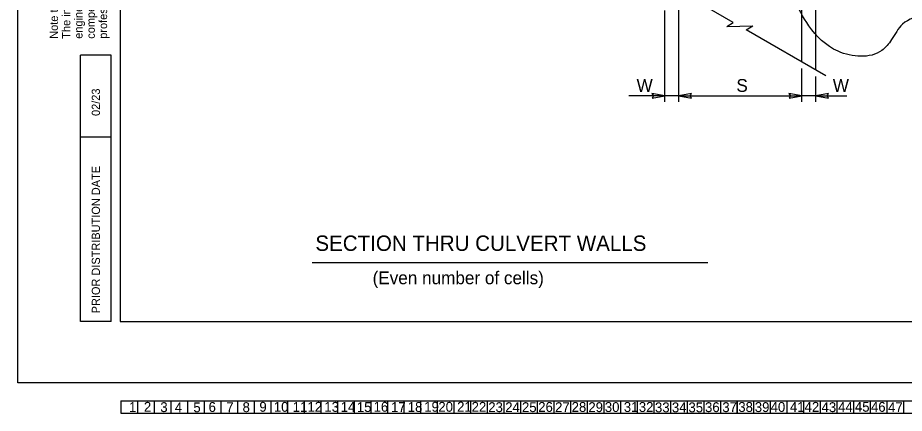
# Model space of a CAD drawing. Extents: x 0 to 2.83, y -0.03 to 1.83.
# Drawn here: x 0 to 0.902, y -0.031 to 0.371 of the extents above; entities that cross this region are included whole.
import ezdxf

# ---------------------------------------------------------------- set-up
doc = ezdxf.new("R2010")
doc.units = 0
for name, color, linetype in [('1', 7, 'Continuous'), ('10', 7, 'Continuous'), ('11', 7, 'Continuous'), ('12', 7, 'Continuous'), ('13', 7, 'Continuous'), ('14', 7, 'Continuous'), ('15', 7, 'Continuous'), ('16', 7, 'Continuous'), ('17', 7, 'Continuous'), ('18', 7, 'Continuous'), ('19', 7, 'Continuous'), ('2', 7, 'Continuous'), ('20', 7, 'Continuous'), ('21', 7, 'Continuous'), ('22', 7, 'Continuous'), ('23', 7, 'Continuous'), ('24', 7, 'Continuous'), ('25', 7, 'Continuous'), ('26', 7, 'Continuous'), ('27', 7, 'Continuous'), ('28', 7, 'Continuous'), ('29', 7, 'Continuous'), ('3', 7, 'Continuous'), ('30', 7, 'Continuous'), ('31', 7, 'Continuous'), ('32', 7, 'Continuous'), ('33', 7, 'Continuous'), ('34', 7, 'Continuous'), ('35', 7, 'Continuous'), ('36', 7, 'Continuous'), ('37', 7, 'Continuous'), ('38', 7, 'Continuous'), ('39', 7, 'Continuous'), ('4', 7, 'Continuous'), ('40', 7, 'Continuous'), ('41', 7, 'Continuous'), ('42', 7, 'Continuous'), ('43', 7, 'Continuous'), ('44', 7, 'Continuous'), ('45', 7, 'Continuous'), ('46', 7, 'Continuous'), ('47', 7, 'Continuous'), ('5', 7, 'Continuous'), ('54', 7, 'Continuous'), ('55', 7, 'Continuous'), ('6', 7, 'Continuous'), ('62', 7, 'Continuous'), ('63', 7, 'Continuous'), ('7', 7, 'Continuous'), ('8', 7, 'Continuous'), ('9', 7, 'Continuous'), ('Default', 7, 'Continuous')]:
    doc.layers.add(name, color=color, linetype=linetype)

msp = doc.modelspace()

# ---------------------------------------------------------------- linework, layer by layer
at = {"layer": '54'}
for points in [[(0.65794, 0.29184), (0.64495, 0.29422), (0.64646, 0.29184), (0.6451, 0.28944)], [(0.67226, 0.29184), (0.68525, 0.28947), (0.68375, 0.29184), (0.6851, 0.29424)], [(0.79726, 0.29184), (0.78427, 0.29422), (0.78578, 0.29184), (0.78442, 0.28944)], [(0.81159, 0.29184), (0.82458, 0.28947), (0.82307, 0.29184), (0.82443, 0.29424)]]:
    msp.add_lwpolyline(points, close=True, dxfattribs=at)
at = {"layer": '55'}
for p, q in [((0.7276, 0.36663), (0.58472, 0.44912)), ((0.65794, 0.28577), (0.65794, 0.37876)), ((0.67226, 0.28577), (0.67226, 0.37951)), ((0.72113, 0.36236), (0.7276, 0.36663)), ((0.72113, 0.36236), (0.74745, 0.36319)), ((0.74097, 0.35891), (0.74745, 0.36319)), ((0.82174, 0.31229), (0.74097, 0.35891)), ((0.79726, 0.28577), (0.79726, 0.31975)), ((0.81159, 0.28577), (0.81159, 0.31148)), ((0.65794, 0.29184), (0.62161, 0.29184)), ((0.67226, 0.29184), (0.65794, 0.29184)), ((0.67226, 0.29184), (0.79726, 0.29184)), ((0.81159, 0.29184), (0.79726, 0.29184)), ((0.81159, 0.29184), (0.84317, 0.29184))]:
    msp.add_line(p, q, dxfattribs=at)
msp.add_spline([(0.95184, 0.37351), (0.94161, 0.37351), (0.92297, 0.37345), (0.89978, 0.36478), (0.88869, 0.34904), (0.87866, 0.33797), (0.83439, 0.3372), (0.80458, 0.36301), (0.77828, 0.42143), (0.75487, 0.48444)], degree=3, dxfattribs=at)
at = {"layer": '62'}
for p, q in [((0.10494, -0.01804), (1.17174, -0.01804)), ((0.10494, -0.01804), (0.10494, -0.03074)), ((0.10496, -0.0181), (1.17175, -0.0181)), ((0.10496, -0.0181), (0.10496, -0.0308)), ((0.12188, -0.01804), (0.12188, -0.03074)), ((0.12189, -0.0181), (0.12189, -0.0308)), ((0.13881, -0.01804), (0.13881, -0.03074)), ((0.13882, -0.0181), (0.13882, -0.0308)), ((0.15574, -0.01804), (0.15574, -0.03074)), ((0.15576, -0.0181), (0.15576, -0.0308)), ((0.17267, -0.01804), (0.17267, -0.03074)), ((0.17269, -0.0181), (0.17269, -0.0308)), ((0.18961, -0.01804), (0.18961, -0.03074)), ((0.18962, -0.0181), (0.18962, -0.0308)), ((0.20654, -0.01804), (0.20654, -0.03074)), ((0.20656, -0.0181), (0.20656, -0.0308)), ((0.22348, -0.01804), (0.22348, -0.03074)), ((0.22349, -0.0181), (0.22349, -0.0308)), ((0.24041, -0.01804), (0.24041, -0.03074)), ((0.24042, -0.0181), (0.24042, -0.0308)), ((0.25734, -0.01804), (0.25734, -0.03074)), ((0.25736, -0.0181), (0.25736, -0.0308)), ((0.27427, -0.01804), (0.27427, -0.03074)), ((0.27429, -0.0181), (0.27429, -0.0308)), ((0.29121, -0.01804), (0.29121, -0.03074)), ((0.29122, -0.0181), (0.29122, -0.0308)), ((0.30814, -0.01804), (0.30814, -0.03074)), ((0.30816, -0.0181), (0.30816, -0.0308)), ((0.32508, -0.01804), (0.32508, -0.03074)), ((0.32509, -0.0181), (0.32509, -0.0308)), ((0.34201, -0.01804), (0.34201, -0.03074)), ((0.34202, -0.0181), (0.34202, -0.0308)), ((0.35894, -0.01804), (0.35894, -0.03074)), ((0.35896, -0.0181), (0.35896, -0.0308)), ((0.37588, -0.01804), (0.37588, -0.03074)), ((0.37589, -0.0181), (0.37589, -0.0308)), ((0.39281, -0.01804), (0.39281, -0.03074)), ((0.39282, -0.0181), (0.39282, -0.0308)), ((0.40974, -0.01804), (0.40974, -0.03074)), ((0.40976, -0.0181), (0.40976, -0.0308)), ((0.42668, -0.01804), (0.42668, -0.03074)), ((0.42669, -0.0181), (0.42669, -0.0308)), ((0.44361, -0.01804), (0.44361, -0.03074)), ((0.44362, -0.0181), (0.44362, -0.0308)), ((0.46054, -0.01804), (0.46054, -0.03074)), ((0.46056, -0.0181), (0.46056, -0.0308)), ((0.47748, -0.01804), (0.47748, -0.03074)), ((0.47749, -0.0181), (0.47749, -0.0308)), ((0.49441, -0.01804), (0.49441, -0.03074)), ((0.49442, -0.0181), (0.49442, -0.0308)), ((0.51134, -0.01804), (0.51134, -0.03074)), ((0.51136, -0.0181), (0.51136, -0.0308)), ((0.52828, -0.01804), (0.52828, -0.03074)), ((0.52829, -0.0181), (0.52829, -0.0308)), ((0.54521, -0.01804), (0.54521, -0.03074)), ((0.54522, -0.0181), (0.54522, -0.0308)), ((0.56214, -0.01804), (0.56214, -0.03074)), ((0.56216, -0.0181), (0.56216, -0.0308)), ((0.57908, -0.01804), (0.57908, -0.03074)), ((0.57909, -0.0181), (0.57909, -0.0308)), ((0.59601, -0.01804), (0.59601, -0.03074)), ((0.59602, -0.0181), (0.59602, -0.0308)), ((0.61294, -0.01804), (0.61294, -0.03074)), ((0.61296, -0.0181), (0.61296, -0.0308)), ((0.62988, -0.01804), (0.62988, -0.03074)), ((0.62989, -0.0181), (0.62989, -0.0308)), ((0.64681, -0.01804), (0.64681, -0.03074)), ((0.64682, -0.0181), (0.64682, -0.0308)), ((0.66374, -0.01804), (0.66374, -0.03074)), ((0.66376, -0.0181), (0.66376, -0.0308)), ((0.68068, -0.01804), (0.68068, -0.03074)), ((0.68069, -0.0181), (0.68069, -0.0308)), ((0.69761, -0.01804), (0.69761, -0.03074)), ((0.69762, -0.0181), (0.69762, -0.0308)), ((0.71454, -0.01804), (0.71454, -0.03074)), ((0.71456, -0.0181), (0.71456, -0.0308)), ((0.73147, -0.01804), (0.73147, -0.03074)), ((0.73149, -0.0181), (0.73149, -0.0308)), ((0.74841, -0.01804), (0.74841, -0.03074)), ((0.74842, -0.0181), (0.74842, -0.0308)), ((0.76534, -0.01804), (0.76534, -0.03074)), ((0.76536, -0.0181), (0.76536, -0.0308)), ((0.78228, -0.01804), (0.78228, -0.03074)), ((0.78229, -0.0181), (0.78229, -0.0308)), ((0.79921, -0.01804), (0.79921, -0.03074)), ((0.79922, -0.0181), (0.79922, -0.0308)), ((0.81614, -0.01804), (0.81614, -0.03074)), ((0.81616, -0.0181), (0.81616, -0.0308)), ((0.83308, -0.01804), (0.83308, -0.03074)), ((0.83309, -0.0181), (0.83309, -0.0308)), ((0.85001, -0.01804), (0.85001, -0.03074)), ((0.85002, -0.0181), (0.85002, -0.0308)), ((0.86694, -0.01804), (0.86694, -0.03074)), ((0.86695, -0.0181), (0.86695, -0.0308)), ((0.88388, -0.01804), (0.88388, -0.03074)), ((0.88389, -0.0181), (0.88389, -0.0308)), ((0.90081, -0.01804), (0.90081, -0.03074)), ((0.90082, -0.0181), (0.90082, -0.0308)), ((0.10494, -0.03074), (1.17174, -0.03074)), ((0.10496, -0.0308), (1.17175, -0.0308))]:
    msp.add_line(p, q, dxfattribs=at)
at = {"layer": '63'}
for p, q in [((0, 0), (0, 1.83333)), ((2.83333, 0), (0, 0))]:
    msp.add_line(p, q, dxfattribs=at)
at = {"layer": 'Default'}
for p, q in [((0.79726, 0.32642), (0.79726, 0.41983)), ((0.81159, 0.31815), (0.81159, 0.41202)), ((0.06381, 0.06244), (0.06381, 0.33328)), ((0.09506, 0.33328), (0.06381, 0.33328)), ((0.09506, 0.06244), (0.09506, 0.33328)), ((0.09506, 0.24994), (0.06381, 0.24994)), ((0.29945, 0.12254), (0.70177, 0.12254)), ((0.09506, 0.06244), (0.06381, 0.06244))]:
    msp.add_line(p, q, dxfattribs=at)
msp.add_lwpolyline([(2.72918, 1.77077), (0.10418, 1.77077), (0.10418, 0.06244), (2.72918, 0.06244)], close=True, dxfattribs=at)

# ---------------------------------------------------------------- texts
at = {"layer": '1'}
for p in [(0.11316, -0.02944), (0.11317, -0.02949)]:
    msp.add_text('1', height=0.01, dxfattribs=at).set_placement(p)
at = {"layer": '10'}
for p in [(0.26046, -0.02928), (0.26047, -0.02934)]:
    msp.add_text('10', height=0.01, dxfattribs=at).set_placement(p)
at = {"layer": '11'}
for p in [(0.2796, -0.02937), (0.27961, -0.02942)]:
    msp.add_text('11', height=0.01, dxfattribs=at).set_placement(p)
at = {"layer": '12'}
for p in [(0.29469, -0.02925), (0.29471, -0.0293)]:
    msp.add_text('12', height=0.01, dxfattribs=at).set_placement(p)
at = {"layer": '13'}
for p in [(0.31181, -0.02928), (0.31182, -0.02933)]:
    msp.add_text('13', height=0.01, dxfattribs=at).set_placement(p)
at = {"layer": '14'}
for p in [(0.32844, -0.02939), (0.32846, -0.02944)]:
    msp.add_text('14', height=0.01, dxfattribs=at).set_placement(p)
at = {"layer": '15'}
for p in [(0.34488, -0.02946), (0.34489, -0.02951)]:
    msp.add_text('15', height=0.01, dxfattribs=at).set_placement(p)
at = {"layer": '16'}
for p in [(0.3619, -0.02918), (0.36191, -0.02923)]:
    msp.add_text('16', height=0.01, dxfattribs=at).set_placement(p)
at = {"layer": '17'}
for p in [(0.3797, -0.02946), (0.37971, -0.02951)]:
    msp.add_text('17', height=0.01, dxfattribs=at).set_placement(p)
at = {"layer": '18'}
for p in [(0.39663, -0.02938), (0.39664, -0.02943)]:
    msp.add_text('18', height=0.01, dxfattribs=at).set_placement(p)
at = {"layer": '19'}
for p in [(0.4134, -0.02918), (0.41342, -0.02923)]:
    msp.add_text('19', height=0.01, dxfattribs=at).set_placement(p)
at = {"layer": '2'}
for p in [(0.12828, -0.02928), (0.12829, -0.02934)]:
    msp.add_text('2', height=0.01, dxfattribs=at).set_placement(p)
at = {"layer": '20'}
for p in [(0.42774, -0.02926), (0.42776, -0.02931)]:
    msp.add_text('20', height=0.01, dxfattribs=at).set_placement(p)
at = {"layer": '21'}
for p in [(0.44688, -0.02909), (0.44689, -0.02914)]:
    msp.add_text('21', height=0.01, dxfattribs=at).set_placement(p)
at = {"layer": '22'}
for p in [(0.46158, -0.02929), (0.46159, -0.02934)]:
    msp.add_text('22', height=0.01, dxfattribs=at).set_placement(p)
at = {"layer": '23'}
for p in [(0.47852, -0.02958), (0.47853, -0.02963)]:
    msp.add_text('23', height=0.01, dxfattribs=at).set_placement(p)
at = {"layer": '24'}
for p in [(0.49576, -0.02958), (0.49577, -0.02963)]:
    msp.add_text('24', height=0.01, dxfattribs=at).set_placement(p)
at = {"layer": '25'}
for p in [(0.51281, -0.02958), (0.51282, -0.02963)]:
    msp.add_text('25', height=0.01, dxfattribs=at).set_placement(p)
at = {"layer": '26'}
for p in [(0.52931, -0.02936), (0.52932, -0.02941)]:
    msp.add_text('26', height=0.01, dxfattribs=at).set_placement(p)
at = {"layer": '27'}
for p in [(0.54648, -0.02958), (0.54649, -0.02963)]:
    msp.add_text('27', height=0.01, dxfattribs=at).set_placement(p)
at = {"layer": '28'}
for p in [(0.56333, -0.02938), (0.56334, -0.02943)]:
    msp.add_text('28', height=0.01, dxfattribs=at).set_placement(p)
at = {"layer": '29'}
for p in [(0.58032, -0.02956), (0.58034, -0.02961)]:
    msp.add_text('29', height=0.01, dxfattribs=at).set_placement(p)
at = {"layer": '3'}
for p in [(0.145, -0.02955), (0.14501, -0.02961)]:
    msp.add_text('3', height=0.01, dxfattribs=at).set_placement(p)
at = {"layer": '30'}
for p in [(0.59706, -0.02946), (0.59707, -0.02951)]:
    msp.add_text('30', height=0.01, dxfattribs=at).set_placement(p)
at = {"layer": '31'}
for p in [(0.61636, -0.02938), (0.61637, -0.02943)]:
    msp.add_text('31', height=0.01, dxfattribs=at).set_placement(p)
at = {"layer": '32'}
for p in [(0.63163, -0.02938), (0.63165, -0.02943)]:
    msp.add_text('32', height=0.01, dxfattribs=at).set_placement(p)
at = {"layer": '33'}
for p in [(0.64808, -0.02978), (0.64809, -0.02983)]:
    msp.add_text('33', height=0.01, dxfattribs=at).set_placement(p)
at = {"layer": '34'}
for p in [(0.66527, -0.02978), (0.66528, -0.02984)]:
    msp.add_text('34', height=0.01, dxfattribs=at).set_placement(p)
at = {"layer": '35'}
for p in [(0.68209, -0.02978), (0.68211, -0.02984)]:
    msp.add_text('35', height=0.01, dxfattribs=at).set_placement(p)
at = {"layer": '36'}
for p in [(0.69895, -0.02958), (0.69896, -0.02964)]:
    msp.add_text('36', height=0.01, dxfattribs=at).set_placement(p)
at = {"layer": '37'}
for p in [(0.71654, -0.02958), (0.71655, -0.02964)]:
    msp.add_text('37', height=0.01, dxfattribs=at).set_placement(p)
at = {"layer": '38'}
for p in [(0.73281, -0.02938), (0.73282, -0.02943)]:
    msp.add_text('38', height=0.01, dxfattribs=at).set_placement(p)
at = {"layer": '39'}
for p in [(0.74958, -0.0295), (0.74959, -0.02955)]:
    msp.add_text('39', height=0.01, dxfattribs=at).set_placement(p)
at = {"layer": '4'}
for p in [(0.15973, -0.02984), (0.15975, -0.0299)]:
    msp.add_text('4', height=0.01, dxfattribs=at).set_placement(p)
at = {"layer": '40'}
for p in [(0.76566, -0.02938), (0.76567, -0.02944)]:
    msp.add_text('40', height=0.01, dxfattribs=at).set_placement(p)
at = {"layer": '41'}
for p in [(0.78528, -0.02938), (0.7853, -0.02943)]:
    msp.add_text('41', height=0.01, dxfattribs=at).set_placement(p)
at = {"layer": '42'}
for p in [(0.8002, -0.0293), (0.80022, -0.02936)]:
    msp.add_text('42', height=0.01, dxfattribs=at).set_placement(p)
at = {"layer": '43'}
for p in [(0.8175, -0.02958), (0.81751, -0.02964)]:
    msp.add_text('43', height=0.01, dxfattribs=at).set_placement(p)
at = {"layer": '44'}
for p in [(0.83425, -0.02949), (0.83427, -0.02955)]:
    msp.add_text('44', height=0.01, dxfattribs=at).set_placement(p)
at = {"layer": '45'}
for p in [(0.85139, -0.02918), (0.8514, -0.02924)]:
    msp.add_text('45', height=0.01, dxfattribs=at).set_placement(p)
at = {"layer": '46'}
for p in [(0.8677, -0.02929), (0.86771, -0.02935)]:
    msp.add_text('46', height=0.01, dxfattribs=at).set_placement(p)
at = {"layer": '47'}
for p in [(0.8852, -0.02958), (0.88522, -0.02964)]:
    msp.add_text('47', height=0.01, dxfattribs=at).set_placement(p)
at = {"layer": '5'}
for p in [(0.17858, -0.02977), (0.17859, -0.02982)]:
    msp.add_text('5', height=0.01, dxfattribs=at).set_placement(p)
at = {"layer": '6'}
for p in [(0.19409, -0.02938), (0.19411, -0.02943)]:
    msp.add_text('6', height=0.01, dxfattribs=at).set_placement(p)
at = {"layer": '63'}
for s, height, p in [('02/23', 0.008333, (0.0836, 0.27145)), ('PRIOR DISTRIBUTION DATE', 0.0083333, (0.0836, 0.07078))]:
    msp.add_text(s, height=height, rotation=90, dxfattribs=at).set_placement(p)
at = {"layer": '7'}
for p in [(0.21211, -0.02964), (0.21212, -0.02969)]:
    msp.add_text('7', height=0.01, dxfattribs=at).set_placement(p)
at = {"layer": '8'}
for p in [(0.22865, -0.02958), (0.22866, -0.02963)]:
    msp.add_text('8', height=0.01, dxfattribs=at).set_placement(p)
at = {"layer": '9'}
for p in [(0.24573, -0.02921), (0.24574, -0.02926)]:
    msp.add_text('9', height=0.01, dxfattribs=at).set_placement(p)
at = {"layer": 'Default'}
for s, height, p in [('The information presented in this Standard Drawing has been prepared in accordance with recognized', 0.0083333, (0.05339, 0.34994)), ('competent professional examination and verification of its suitability and applicability by a licensed', 0.00833333, (0.07839, 0.34994)), ('engineering principles and is for general use. It should not be used for specific application without', 0.00833333, (0.06589, 0.34994)), ('professional engineer. Contents within the inner border line shall not be altered.', 0.0083333, (0.09089, 0.34994)), ('Note to Designer:', 0.0083333, (0.04089, 0.34994))]:
    msp.add_text(s, height=height, rotation=90, dxfattribs=at).set_placement(p)
for s, height, p in [('W', 0.01302, (0.62936, 0.29596)), ('S', 0.01302, (0.73083, 0.29596)), ('W', 0.01302, (0.8289, 0.29596)), ('SECTION THRU CULVERT WALLS', 0.015625, (0.3027, 0.13429)), ('(Even number of cells)', 0.0130208, (0.36089, 0.10038))]:
    msp.add_text(s, height=height, dxfattribs=at).set_placement(p)

doc.saveas('drawing.dxf')
